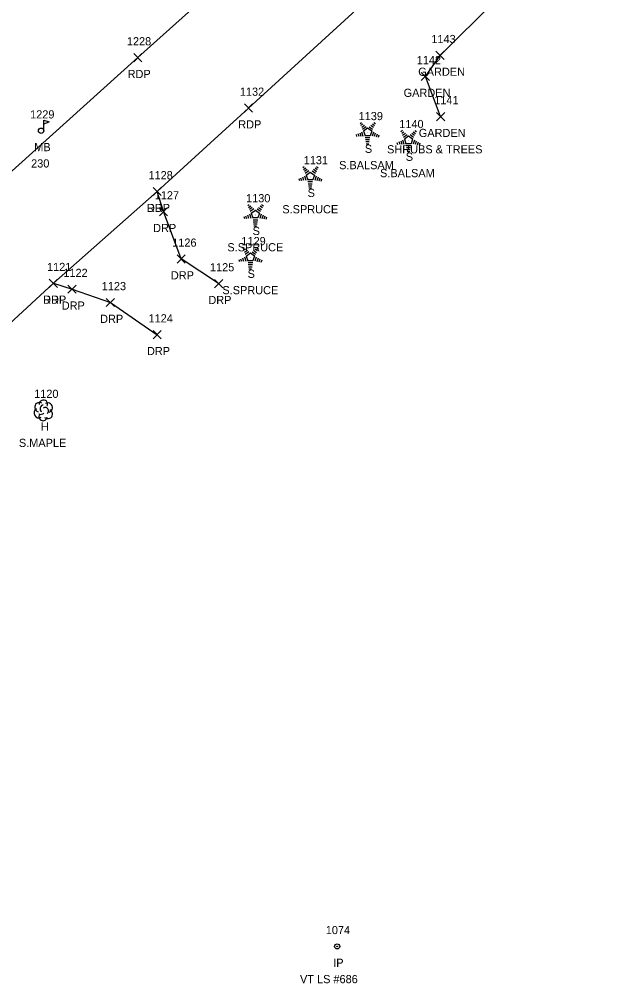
# Model space of a CAD drawing. Extents: x 1496556 to 1498241, y 599216 to 604470.
# Drawn here: x 1497403.3 to 1497547.4, y 602932.5 to 603168.8 of the extents above; entities that cross this region are included whole.
import ezdxf

# ---------------------------------------------------------------- set-up
doc = ezdxf.new("R2010")
doc.units = 0
for name, color, linetype in [('L_A', 7, 'Continuous'), ('L_C', 7, 'Continuous'), ('L_I', 7, 'Continuous'), ('L_TIC', 7, 'Continuous'), ('LAPB', 7, 'Continuous'), ('LMB', 7, 'Continuous'), ('LTC', 7, 'Continuous'), ('LTD', 7, 'Continuous'), ('M_A', 7, 'Continuous'), ('M_C', 7, 'Continuous'), ('M_I', 7, 'Continuous'), ('MPIR', 7, 'Continuous'), ('P_A', 7, 'Continuous'), ('P_I', 7, 'Continuous'), ('P_TIC', 7, 'Continuous'), ('PET', 7, 'Continuous'), ('R_A', 7, 'Continuous'), ('R_I', 7, 'Continuous'), ('R_TIC', 7, 'Continuous'), ('RDP', 7, 'Continuous')]:
    doc.layers.add(name, color=color, linetype=linetype)

msp = doc.modelspace()

# ---------------------------------------------------------------- linework, layer by layer
at = {"layer": 'L_TIC'}
for points in [[(1497505.17, 603159.03), (1497507.17, 603161.03)], [(1497507.17, 603159.03), (1497505.17, 603161.03)], [(1497501.6, 603153.88), (1497503.6, 603155.88)], [(1497503.6, 603153.88), (1497501.6, 603155.88)], [(1497505.31, 603144.06), (1497507.31, 603146.06)], [(1497507.31, 603144.06), (1497505.31, 603146.06)]]:
    msp.add_lwpolyline(points, dxfattribs=at)
at = {"layer": 'LAPB'}
msp.add_lwpolyline([(1497506.31, 603145.06), (1497502.6, 603154.88), (1497506.17, 603160.03), (1497533.3, 603186.99), (1497539.67, 603185.79)], dxfattribs=at)
at = {"layer": 'LMB'}
for p, q in [((1497409.26, 603144.2), (1497410.55, 603143.81)), ((1497409.27, 603141.6), (1497409.26, 603144.2)), ((1497409.26, 603143.3), (1497410.55, 603143.81)), ((1497408.61, 603141.6), (1497408.61, 603141.6))]:
    msp.add_line(p, q, dxfattribs=at)
msp.add_circle((1497408.61, 603141.6), 0.656, dxfattribs=at)
at = {"layer": 'LTC'}
for p, q in [((1497486.6, 603143.39), (1497486.95, 603143.65)), ((1497486.81, 603142.93), (1497487.34, 603143.31)), ((1497489.62, 603143.29), (1497490.17, 603142.89)), ((1497490, 603143.64), (1497490.41, 603143.33)), ((1497486.09, 603140.89), (1497486.3, 603140.24)), ((1497486.54, 603141.11), (1497486.81, 603140.27)), ((1497487, 603141.32), (1497487.33, 603140.3)), ((1497487.02, 603142.46), (1497487.72, 603142.97)), ((1497487.23, 603142), (1497488.1, 603142.64)), ((1497487.45, 603141.54), (1497488.46, 603142.28)), ((1497487.45, 603141.54), (1497487.84, 603140.35)), ((1497488.46, 603142.28), (1497489.46, 603141.55)), ((1497488.88, 603142.59), (1497489.69, 603142)), ((1497489.46, 603141.55), (1497489.07, 603140.35)), ((1497489.25, 603142.94), (1497489.93, 603142.44)), ((1497489.9, 603141.28), (1497489.56, 603140.24)), ((1497490.34, 603141.03), (1497490.05, 603140.15)), ((1497496.61, 603141.45), (1497496.97, 603141.7)), ((1497496.82, 603140.98), (1497497.35, 603141.36)), ((1497497.03, 603140.51), (1497497.74, 603141.03)), ((1497499.27, 603140.99), (1497499.95, 603140.5)), ((1497499.64, 603141.34), (1497500.19, 603140.94)), ((1497500.01, 603141.69), (1497500.43, 603141.38)), ((1497485.63, 603140.67), (1497485.78, 603140.21)), ((1497489.07, 603140.35), (1497487.84, 603140.35)), ((1497489.03, 603139.85), (1497487.89, 603139.85)), ((1497488.95, 603139.35), (1497487.96, 603139.35)), ((1497488.86, 603138.85), (1497488.03, 603138.85)), ((1497490.79, 603140.78), (1497490.55, 603140.05)), ((1497491.23, 603140.53), (1497491.04, 603139.96)), ((1497495.64, 603138.72), (1497495.8, 603138.26)), ((1497496.1, 603138.94), (1497496.31, 603138.29)), ((1497496.56, 603139.16), (1497496.83, 603138.32)), ((1497497.01, 603139.37), (1497497.34, 603138.35)), ((1497497.24, 603140.05), (1497498.12, 603140.69)), ((1497497.47, 603139.59), (1497498.48, 603140.33)), ((1497497.47, 603139.59), (1497497.85, 603138.4)), ((1497498.48, 603140.33), (1497499.47, 603139.6)), ((1497498.9, 603140.64), (1497499.71, 603140.05)), ((1497499.47, 603139.6), (1497499.08, 603138.4)), ((1497499.91, 603139.33), (1497499.57, 603138.29)), ((1497500.36, 603139.08), (1497500.07, 603138.2)), ((1497500.8, 603138.83), (1497500.56, 603138.1)), ((1497501.24, 603138.58), (1497501.06, 603138.01)), ((1497488.78, 603138.35), (1497488.1, 603138.35)), ((1497499.08, 603138.4), (1497497.85, 603138.4)), ((1497499.04, 603137.9), (1497497.9, 603137.9)), ((1497498.96, 603137.4), (1497497.97, 603137.4)), ((1497498.88, 603136.9), (1497498.05, 603136.9)), ((1497498.79, 603136.4), (1497498.12, 603136.4)), ((1497472.59, 603132.61), (1497472.94, 603132.87)), ((1497472.8, 603132.15), (1497473.33, 603132.53)), ((1497473.01, 603131.68), (1497473.71, 603132.19)), ((1497473.22, 603131.21), (1497474.09, 603131.85)), ((1497473.44, 603130.76), (1497474.45, 603131.49)), ((1497474.45, 603131.49), (1497475.45, 603130.77)), ((1497474.87, 603131.81), (1497475.68, 603131.22)), ((1497475.24, 603132.16), (1497475.92, 603131.66)), ((1497475.61, 603132.5), (1497476.16, 603132.1)), ((1497475.99, 603132.85), (1497476.4, 603132.55)), ((1497471.62, 603129.89), (1497471.77, 603129.42)), ((1497472.07, 603130.11), (1497472.29, 603129.46)), ((1497472.53, 603130.32), (1497472.8, 603129.49)), ((1497472.99, 603130.54), (1497473.32, 603129.52)), ((1497473.44, 603130.76), (1497473.83, 603129.57)), ((1497475.06, 603129.57), (1497473.83, 603129.57)), ((1497475.45, 603130.77), (1497475.06, 603129.57)), ((1497475.89, 603130.5), (1497475.55, 603129.46)), ((1497476.33, 603130.25), (1497476.04, 603129.36)), ((1497476.78, 603130), (1497476.54, 603129.27)), ((1497477.22, 603129.75), (1497477.03, 603129.17)), ((1497475.02, 603129.07), (1497473.87, 603129.07)), ((1497474.94, 603128.57), (1497473.95, 603128.57)), ((1497474.85, 603128.07), (1497474.02, 603128.07)), ((1497474.77, 603127.57), (1497474.09, 603127.57)), ((1497459.14, 603123.31), (1497459.5, 603123.56)), ((1497459.35, 603122.84), (1497459.88, 603123.23)), ((1497459.56, 603122.38), (1497460.26, 603122.89)), ((1497459.77, 603121.91), (1497460.65, 603122.55)), ((1497460, 603121.45), (1497461.01, 603122.19)), ((1497461.01, 603122.19), (1497462, 603121.46)), ((1497461.43, 603122.5), (1497462.24, 603121.91)), ((1497461.8, 603122.85), (1497462.48, 603122.36)), ((1497462.17, 603123.2), (1497462.72, 603122.8)), ((1497462.54, 603123.55), (1497462.96, 603123.24)), ((1497458.17, 603120.59), (1497458.33, 603120.12)), ((1497458.63, 603120.8), (1497458.84, 603120.15)), ((1497459.09, 603121.02), (1497459.36, 603120.18)), ((1497459.54, 603121.24), (1497459.87, 603120.22)), ((1497460, 603121.45), (1497460.38, 603120.26)), ((1497461.61, 603120.26), (1497460.38, 603120.26)), ((1497461.57, 603119.76), (1497460.43, 603119.76)), ((1497462, 603121.46), (1497461.61, 603120.26)), ((1497462.44, 603121.19), (1497462.1, 603120.15)), ((1497462.89, 603120.94), (1497462.6, 603120.06)), ((1497463.33, 603120.69), (1497463.09, 603119.96)), ((1497463.77, 603120.44), (1497463.59, 603119.87)), ((1497461.49, 603119.26), (1497460.5, 603119.26)), ((1497461.41, 603118.76), (1497460.58, 603118.76)), ((1497461.32, 603118.26), (1497460.65, 603118.26)), ((1497457.92, 603112.81), (1497458.28, 603113.07)), ((1497458.13, 603112.35), (1497458.66, 603112.73)), ((1497460.95, 603112.71), (1497461.5, 603112.31)), ((1497461.32, 603113.05), (1497461.74, 603112.75)), ((1497457.41, 603110.31), (1497457.62, 603109.66)), ((1497457.87, 603110.53), (1497458.14, 603109.69)), ((1497458.32, 603110.74), (1497458.65, 603109.72)), ((1497458.34, 603111.88), (1497459.05, 603112.39)), ((1497458.55, 603111.42), (1497459.43, 603112.05)), ((1497458.78, 603110.96), (1497459.79, 603111.7)), ((1497458.78, 603110.96), (1497459.16, 603109.77)), ((1497459.79, 603111.7), (1497460.78, 603110.97)), ((1497460.21, 603112.01), (1497461.02, 603111.42)), ((1497460.78, 603110.97), (1497460.39, 603109.77)), ((1497460.58, 603112.36), (1497461.26, 603111.86)), ((1497461.22, 603110.7), (1497460.88, 603109.66)), ((1497461.67, 603110.45), (1497461.38, 603109.57)), ((1497462.11, 603110.2), (1497461.87, 603109.47)), ((1497456.95, 603110.09), (1497457.11, 603109.62)), ((1497460.39, 603109.77), (1497459.16, 603109.77)), ((1497460.35, 603109.27), (1497459.21, 603109.27)), ((1497460.27, 603108.77), (1497459.28, 603108.77)), ((1497460.19, 603108.27), (1497459.36, 603108.27)), ((1497462.56, 603109.95), (1497462.37, 603109.38)), ((1497460.1, 603107.77), (1497459.43, 603107.77))]:
    msp.add_line(p, q, dxfattribs=at)
at = {"layer": 'LTD'}
msp.add_line((1497409.11, 603073.26), (1497409.11, 603073.26), dxfattribs=at)
msp.add_line((1497409.11, 603073.26), (1497409.11, 603073.26), dxfattribs=at)
msp.add_arc((1497409.16, 603074.69), 1.05, 335.5272, 180.9563, dxfattribs=at)
for centre, major_axis, ratio, start_param, end_param in [((1497408.32, 603073.92), (1.21, -0.51), 0.895232, 1.570796, 4.712389), ((1497410.15, 603073.84), (-1.14, -0.48), 0.949671, 1.570796, 4.712389), ((1497408.03, 603072.55), (0.58, -1.04), 0.959034, 3.141593, 6.283185), ((1497408.65, 603072.51), (-0.625, -0.083), 0.423636, 0, 3.141593), ((1497408.9, 603073.71), (-0.208, -0.792), 0.645439, 3.141593, 6.283185), ((1497409.61, 603073.09), (-0.5, 0.667), 0.989748, 3.141593, 6.283185), ((1497410.11, 603072.42), (-1.09, 0.79), 0.841452, 1.570796, 4.712389), ((1497409.11, 603071.76), (0.26, 1.06), 0.942809, 1.570796, 4.712389)]:
    msp.add_ellipse(centre, major_axis=major_axis, ratio=ratio, start_param=start_param, end_param=end_param, dxfattribs=at)
at = {"layer": 'MPIR'}
for radius in [0.625, 0.0833]:
    msp.add_circle((1497481.01, 602942.11), radius, dxfattribs=at)
at = {"layer": 'P_TIC'}
for points in [[(1497431.27, 603158.48), (1497433.27, 603160.48)], [(1497433.27, 603158.48), (1497431.27, 603160.48)], [(1497458.34, 603146.15), (1497460.34, 603148.15)], [(1497460.34, 603146.15), (1497458.34, 603148.15)], [(1497435.99, 603125.72), (1497437.99, 603127.72)], [(1497437.99, 603125.72), (1497435.99, 603127.72)], [(1497410.61, 603103.29), (1497412.61, 603105.29)], [(1497412.61, 603103.29), (1497410.61, 603105.29)]]:
    msp.add_lwpolyline(points, dxfattribs=at)
at = {"layer": 'PET'}
for points in [[(1497580.33, 603293.36), (1497544.07, 603260.5), (1497503.96, 603223.83), (1497469.44, 603192.83), (1497432.27, 603159.48), (1497398.1, 603128.8), (1497361.66, 603094.11), (1497332.15, 603067.83), (1497309.09, 603046.17), (1497294.72, 603034.46), (1497285.78, 603029.77), (1497276.79, 603028.23), (1497267.28, 603029.35), (1497255.38, 603035.01), (1497245.34, 603044.47)], [(1497277.08, 602932.51), (1497278.76, 602955.27), (1497283.83, 602972.38), (1497292.85, 602989.5), (1497302.51, 603001.53), (1497319.84, 603019.72), (1497338.13, 603037.05), (1497360.02, 603057.19), (1497386.8, 603081.38), (1497411.61, 603104.29), (1497436.99, 603126.72), (1497459.34, 603147.15), (1497493.2, 603178.11), (1497522.29, 603204.31), (1497552.95, 603231.97)]]:
    msp.add_lwpolyline(points, dxfattribs=at)
at = {"layer": 'R_TIC'}
for points in [[(1497435.99, 603125.72), (1497437.99, 603127.72)], [(1497437.99, 603125.72), (1497435.99, 603127.72)], [(1497437.52, 603120.81), (1497439.52, 603122.81)], [(1497439.52, 603120.81), (1497437.52, 603122.81)], [(1497441.85, 603109.24), (1497443.85, 603111.24)], [(1497443.85, 603109.24), (1497441.85, 603111.24)], [(1497410.61, 603103.29), (1497412.61, 603105.29)], [(1497412.61, 603103.29), (1497410.61, 603105.29)], [(1497415.16, 603101.84), (1497417.16, 603103.84)], [(1497417.16, 603101.84), (1497415.16, 603103.84)], [(1497451.02, 603103.21), (1497453.02, 603105.21)], [(1497453.02, 603103.21), (1497451.02, 603105.21)], [(1497424.55, 603098.6), (1497426.55, 603100.6)], [(1497426.55, 603098.6), (1497424.55, 603100.6)], [(1497436, 603090.72), (1497438, 603092.72)], [(1497438, 603090.72), (1497436, 603092.72)]]:
    msp.add_lwpolyline(points, dxfattribs=at)
at = {"layer": 'RDP'}
for points in [[(1497452.02, 603104.21), (1497442.85, 603110.24), (1497438.52, 603121.81), (1497436.99, 603126.72)], [(1497411.61, 603104.29), (1497416.16, 603102.84), (1497425.55, 603099.6), (1497437, 603091.72)]]:
    msp.add_lwpolyline(points, dxfattribs=at)

# ---------------------------------------------------------------- texts
at = {"layer": 'L_A'}
for s, p in [('GARDEN', (1497500.84, 603155.03)), ('GARDEN', (1497497.27, 603149.88)), ('GARDEN', (1497500.98, 603140.06)), ('MB', (1497406.92, 603136.6)), ('S', (1497487.79, 603136.19)), ('S', (1497497.8, 603134.24)), ('S', (1497473.78, 603125.4)), ('S', (1497460.33, 603116.1)), ('S', (1497459.11, 603105.61)), ('H', (1497408.54, 603068.26))]:
    msp.add_text(s, height=2, dxfattribs=at).set_placement(p)
at = {"layer": 'L_C'}
for s, p in [('SHRUBS & TREES', (1497493.22, 603136.06)), ('230', (1497406.16, 603132.6)), ('S.BALSAM', (1497481.49, 603132.19)), ('S.BALSAM', (1497491.5, 603130.24)), ('S.SPRUCE', (1497467.6, 603121.4)), ('S.SPRUCE', (1497454.16, 603112.1)), ('S.SPRUCE', (1497452.94, 603101.61)), ('S.MAPLE', (1497403.17, 603064.26))]:
    msp.add_text(s, height=2, dxfattribs=at).set_placement(p)
at = {"layer": 'L_I'}
for s, p in [('1143', (1497504.05, 603163.03)), ('1142', (1497500.47, 603157.88)), ('1141', (1497504.75, 603148.06)), ('1229', (1497405.91, 603144.6)), ('1139', (1497486.27, 603144.19)), ('1140', (1497496.2, 603142.24)), ('1131', (1497472.83, 603133.4)), ('1130', (1497458.73, 603124.1)), ('1129', (1497457.59, 603113.61)), ('1120', (1497406.9, 603076.26))]:
    msp.add_text(s, height=2, dxfattribs=at).set_placement(p)
at = {"layer": 'LTC'}
for p in [(1497488.34, 603141.29), (1497498.36, 603139.34), (1497474.33, 603130.51), (1497460.89, 603121.2), (1497459.67, 603110.71)]:
    msp.add_text('.', height=1.04, rotation=270, dxfattribs=at).set_placement(p)
at = {"layer": 'M_A'}
msp.add_text('IP', height=2, dxfattribs=at).set_placement((1497480.05, 602937.11))
at = {"layer": 'M_C'}
msp.add_text('VT LS #686', height=2, dxfattribs=at).set_placement((1497471.93, 602933.11))
at = {"layer": 'M_I'}
msp.add_text('1074', height=2, dxfattribs=at).set_placement((1497478.23, 602945.11))
at = {"layer": 'P_A'}
for p in [(1497429.76, 603154.48), (1497456.82, 603142.15), (1497434.48, 603121.72), (1497409.1, 603099.29)]:
    msp.add_text('RDP', height=2, dxfattribs=at).set_placement(p)
at = {"layer": 'P_I'}
for s, p in [('1228', (1497429.58, 603162.48)), ('1132', (1497457.21, 603150.15)), ('1128', (1497434.86, 603129.72)), ('1121', (1497410.05, 603107.29))]:
    msp.add_text(s, height=2, dxfattribs=at).set_placement(p)
at = {"layer": 'R_A'}
for p in [(1497434.48, 603121.72), (1497436, 603116.81), (1497440.34, 603105.24), (1497409.1, 603099.29), (1497449.51, 603099.21), (1497413.65, 603097.84), (1497423.04, 603094.6), (1497434.49, 603086.72)]:
    msp.add_text('DRP', height=2, dxfattribs=at).set_placement(p)
at = {"layer": 'R_I'}
for s, p in [('1128', (1497434.86, 603129.72)), ('1127', (1497436.39, 603124.81)), ('1126', (1497440.67, 603113.24)), ('1121', (1497410.05, 603107.29)), ('1122', (1497414.04, 603105.84)), ('1125', (1497449.9, 603107.21)), ('1123', (1497423.43, 603102.6)), ('1124', (1497434.88, 603094.72))]:
    msp.add_text(s, height=2, dxfattribs=at).set_placement(p)

doc.saveas('drawing.dxf')
